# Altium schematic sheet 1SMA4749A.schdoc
size 127 x 101 mm
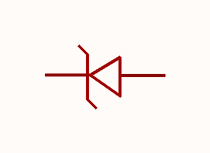
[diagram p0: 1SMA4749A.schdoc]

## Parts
D?  1sma4749a_c173489  [SMA_L4.4-W2.8-LS5.4-RD]  (value not drawn)

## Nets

Not connected (* = marked no-connect by the designer): D? 1(K) 2(A)

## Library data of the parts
D? = 1sma4749a_c173489: 二极管配置:1个独立式;稳压值(标称值):24V;稳压值(范围):22.8V~26V;耗散功率(Pd):1W;; Manufacturer: MDD(辰达半导体); AddInBom: yes; ModelId: 4f1e9ef2303f48b48aa8ce0cacf8d7b1; ModelTransform: 204.724,102.362,0,0,0,0,0,0,0; Diode Configuration: 1个独立式; Zener Voltage(Nom): 24V; Reverse Leakage Current (Ir): 5uA; Pd - Power Dissipation: 1W; Impedance(Zzt): 25Ω; Operating Junction Temperature Range: -55℃~+150℃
